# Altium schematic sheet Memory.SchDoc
size A4
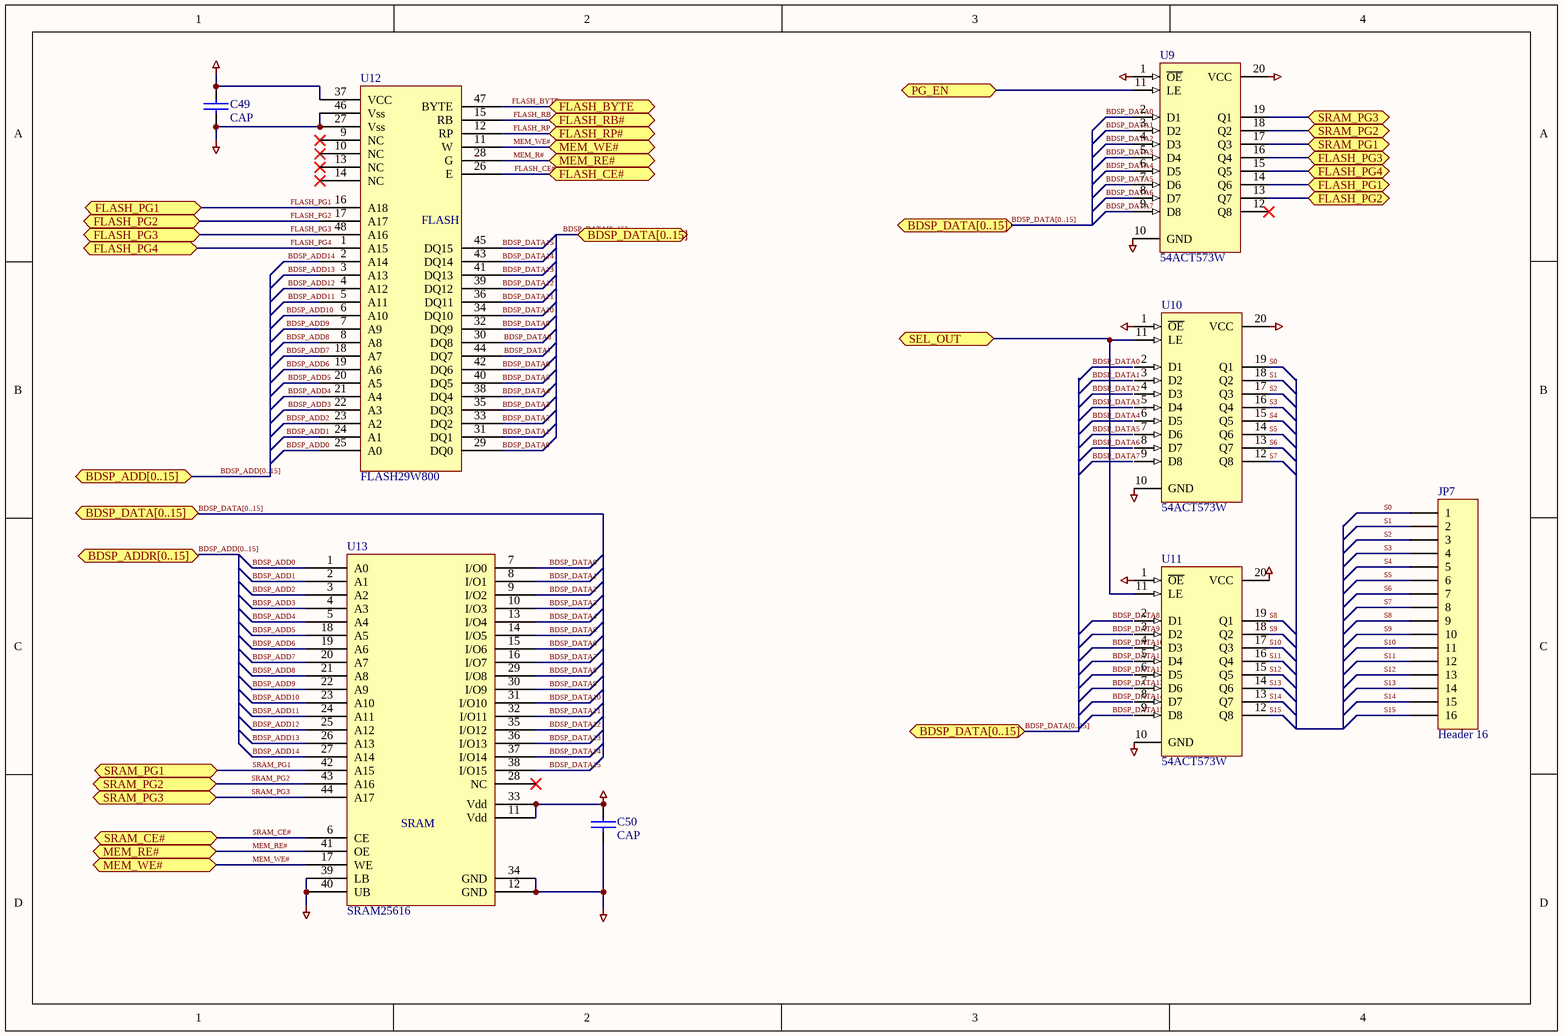
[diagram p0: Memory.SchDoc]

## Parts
C49  CAP  [CC2012-0805]
C50  CAP  [CC2012-0805]
JP7  Header 16  [HDR1X16]
U9  54ACT573W  [CDFP-G20/C10]
U10  54ACT573W  [CDFP-G20/C10]
U11  54ACT573W  [CDFP-G20/C10]
U12  FLASH29W800  [TSSO12X20-G48/P.5]
U13  SRAM25616  [TSOP44]

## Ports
BDSP_ADD[0..15], BDSP_ADDR[0..15], BDSP_DATA[0..15], FLASH_BYTE, FLASH_CE#, FLASH_PG1, FLASH_PG2, FLASH_PG3, FLASH_PG4, FLASH_RB#, FLASH_RP#, MEM_RE#, MEM_WE#, PG_EN, SEL_OUT, SRAM_CE#, SRAM_PG1, SRAM_PG2, SRAM_PG3

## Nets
3.3V: C49.1 C50.1 U12.37(VCC) U13.11(Vdd) U13.33(Vdd)
5v: U9.20(VCC) U10.20(VCC) U11.20(VCC)
DGND: C49.2 C50.2 U9.1(~{OE}) U9.10(GND) U10.1(~{OE}) U10.10(GND) U11.1(~{OE}) U11.10(GND) U12.27(Vss) U12.46(Vss) U13.12(GND) U13.34(GND) U13.39(LB) U13.40(UB)
BDSP_ADD0: U12.25(A0) U13.1(A0)
BDSP_ADD1: U12.24(A1) U13.2(A1)
BDSP_ADD2: U12.23(A2) U13.3(A2)
BDSP_ADD3: U12.22(A3) U13.4(A3)
BDSP_ADD4: U12.21(A4) U13.5(A4)
BDSP_ADD5: U12.20(A5) U13.18(A5)
BDSP_ADD6: U12.19(A6) U13.19(A6)
BDSP_ADD7: U12.18(A7) U13.20(A7)
BDSP_ADD8: U12.8(A8) U13.21(A8)
BDSP_ADD9: U12.7(A9) U13.22(A9)
BDSP_ADD10: U12.6(A10) U13.23(A10)
BDSP_ADD11: U12.5(A11) U13.24(A11)
BDSP_ADD12: U12.4(A12) U13.25(A12)
BDSP_ADD13: U12.3(A13) U13.26(A13)
BDSP_ADD14: U12.2(A14) U13.27(A14)
BDSP_DATA0: U9.2(D1) U12.29(DQ0) U13.7(I/O0)
BDSP_DATA1: U9.3(D2) U12.31(DQ1) U13.8(I/O1)
BDSP_DATA2: U9.4(D3) U12.33(DQ2) U13.9(I/O2)
BDSP_DATA3: U9.5(D4) U12.35(DQ3) U13.10(I/O3)
BDSP_DATA4: U9.6(D5) U12.38(DQ4) U13.13(I/O4)
BDSP_DATA5: U9.7(D6) U12.40(DQ5) U13.14(I/O5)
BDSP_DATA6: U9.8(D7) U12.42(DQ6) U13.15(I/O6)
BDSP_DATA7: U9.9(D8) U12.44(DQ7) U13.16(I/O7)
BDSP_DATA8: U12.30(DQ8) U13.29(I/O8)
BDSP_DATA9: U12.32(DQ9) U13.30(I/O9)
BDSP_DATA10: U12.34(DQ10) U13.31(I/O10)
BDSP_DATA11: U12.36(DQ11) U13.32(I/O11)
BDSP_DATA12: U12.39(DQ12) U13.35(I/O12)
BDSP_DATA13: U12.41(DQ13) U13.36(I/O13)
BDSP_DATA14: U12.43(DQ14) U13.37(I/O14)
BDSP_DATA15: U12.45(DQ15) U13.38(I/O15)
FLASH_BYTE: U12.47(BYTE) ; port FLASH_BYTE
FLASH_CE#: U12.26(E) ; port FLASH_CE#
FLASH_PG1: U9.14(Q6) U12.16(A18) ; port FLASH_PG1
FLASH_PG2: U9.13(Q7) U12.17(A17) ; port FLASH_PG2
FLASH_PG3: U9.16(Q4) U12.48(A16) ; port FLASH_PG3
FLASH_PG4: U9.15(Q5) U12.1(A15) ; port FLASH_PG4
FLASH_RB: U12.15(RB) ; port FLASH_RB#
FLASH_RP: U12.12(RP) ; port FLASH_RP#
MEM_R#: U12.28(G) U13.41(OE) ; port MEM_RE#  [also labelled MEM_RE#]
MEM_WE#: U12.11(W) U13.17(WE) ; port MEM_WE#
PG_EN: U9.11(LE) ; port PG_EN
S0: JP7.1 U10.19(Q1)
S1: JP7.2 U10.18(Q2)
S2: JP7.3 U10.17(Q3)
S3: JP7.4 U10.16(Q4)
S4: JP7.5 U10.15(Q5)
S5: JP7.6 U10.14(Q6)
S6: JP7.7 U10.13(Q7)
S7: JP7.8 U10.12(Q8)
S8: JP7.9 U11.19(Q1)
S9: JP7.10 U11.18(Q2)
S10: JP7.11 U11.17(Q3)
S11: JP7.12 U11.16(Q4)
S12: JP7.13 U11.15(Q5)
S13: JP7.14 U11.14(Q6)
S14: JP7.15 U11.13(Q7)
S15: JP7.16 U11.12(Q8)
SEL_OUT: U10.11(LE) U11.11(LE) ; port SEL_OUT
SRAM_CE#: U13.6(CE) ; port SRAM_CE#
SRAM_PG1: U9.17(Q3) U13.42(A15) ; port SRAM_PG1
SRAM_PG2: U9.18(Q2) U13.43(A16) ; port SRAM_PG2
SRAM_PG3: U9.19(Q1) U13.44(A17) ; port SRAM_PG3

Not connected (* = marked no-connect by the designer): U9 12(Q8); U10 2(D1) 3(D2) 4(D3) 5(D4) 6(D5) 7(D6) 8(D7) 9(D8); U11 2(D1) 3(D2) 4(D3) 5(D4) 6(D5) 7(D6) 8(D7) 9(D8); U12 9(NC)* 10(NC)* 13(NC)* 14(NC)*; U13 28(NC)*

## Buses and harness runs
bus BDSP_ADD[0..15]
bus BDSP_ADD[0..15] = port BDSP_ADD[0..15]
bus BDSP_DATA[0..15]
bus BDSP_DATA[0..15] = port BDSP_DATA[0..15]

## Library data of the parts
C49 C50 = CAP: Capacitor
JP7 = Header 16: Header, 16-Pin; Manufacturer: Generic Components; Class I: Connector
U9-U11 = 54ACT573W: Octal D-Type Transparent Latch with 3-State Outputs; Manufacturer: Texas Instruments; Package Information: Latest Revision: Jan-1995; Class I: Logic
U12 = FLASH29W800: FLASH RAM
U13 = SRAM25616: SRAM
